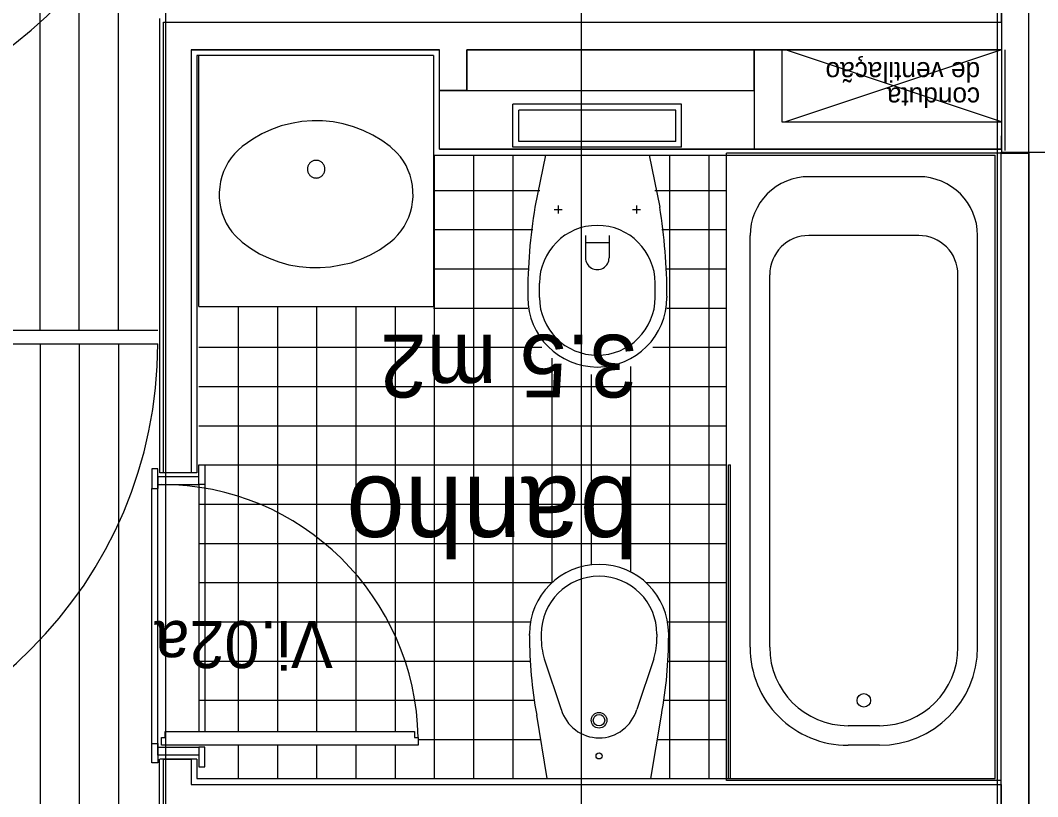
# Model space of a CAD drawing. Extents: x 1248 to 1356, y -443 to -224.
# Drawn here: x 1288.603 to 1291.197, y -234.765 to -232.785 of the extents above; entities that cross this region are included whole.
import ezdxf

# ---------------------------------------------------------------- set-up
doc = ezdxf.new("R2010")
doc.units = 0
for name, color, linetype in [('corte', 7, 'Continuous'), ('estereoctomias', 7, 'Continuous'), ('Level 1', 7, 'Continuous'), ('Level 10', 7, 'Continuous'), ('Level 11', 7, 'Continuous'), ('Level 13', 7, 'Continuous'), ('Level 2', 7, 'Continuous'), ('Level 36', 7, 'Continuous'), ('Level 4', 7, 'Continuous'), ('Level 40', 7, 'Continuous'), ('Level 41', 7, 'Continuous'), ('Level 60', 7, 'Continuous'), ('revestimentos', 7, 'Continuous'), ('vermelhos-tracej', 7, 'Continuous')]:
    doc.layers.add(name, color=color, linetype=linetype)

msp = doc.modelspace()

# ---------------------------------------------------------------- linework, layer by layer
at = {"layer": 'corte'}
for p, q in [((1289.6716, -233.114), (1289.6716, -232.8603)), ((1289.7416, -232.964), (1289.7416, -232.8603)), ((1290.4742, -232.8603), (1290.4742, -233.114)), ((1290.5442, -232.8603), (1291.1042, -232.8603)), ((1290.5442, -232.8603), (1290.5442, -233.044))]:
    msp.add_line(p, q, dxfattribs=at)
msp.add_lwpolyline([(1291.1042, -233.1214), (1291.3342, -233.1214), (1291.3342, -232.3214), (1291.1042, -232.3214)], close=True, dxfattribs=at)
at = {"layer": 'estereoctomias'}
for points in [[(1291.1042, -232.8603), (1289.7416, -232.8603), (1289.7416, -232.964), (1289.6716, -232.964), (1289.6716, -232.8603), (1289.0386, -232.8603), (1289.0386, -233.939), (1288.9686, -233.939), (1288.9686, -232.7903), (1291.1042, -232.7903)], [(1291.1036, -233.114), (1290.4742, -233.114), (1289.6716, -233.114), (1289.6716, -232.964), (1290.4742, -232.964), (1290.4742, -232.8603), (1290.5442, -232.8603), (1290.5442, -233.044), (1291.1042, -233.044)], [(1291.1036, -233.124), (1291.1742, -233.124), (1291.1742, -238.1712), (1291.1042, -238.1713), (1291.1042, -237.4452)], [(1291.1035, -235.0576), (1290.4836, -235.0576), (1290.4836, -234.804), (1289.0385, -234.804), (1289.0385, -234.904), (1288.9685, -234.904), (1288.9685, -234.669), (1289.0386, -234.669), (1289.0386, -234.734), (1291.1035, -234.734), (1291.1035, -234.804), (1290.5536, -234.804), (1290.5536, -234.9876), (1291.1035, -234.9876)]]:
    msp.add_lwpolyline(points, close=True, dxfattribs=at)
at = {"layer": 'Level 1'}
for p, q in [((1291.1042, -232.7903), (1291.1042, -228.764)), ((1291.1742, -239.234), (1291.1742, -228.764)), ((1288.9685, -232.7903), (1291.1042, -232.7903)), ((1288.9686, -233.939), (1288.9686, -232.7903)), ((1289.0386, -232.8603), (1289.0386, -233.939)), ((1289.0386, -232.8603), (1289.6716, -232.8603)), ((1289.7416, -232.8603), (1290.4742, -232.8603)), ((1290.5442, -232.8603), (1291.1042, -232.8603)), ((1291.1135, -233.1176), (1291.1135, -232.8603)), ((1289.6716, -232.964), (1290.4742, -232.964)), ((1290.5442, -233.044), (1291.1042, -233.044)), ((1289.6716, -233.114), (1291.1036, -233.114)), ((1291.1035, -234.804), (1291.1035, -233.1214)), ((1289.0536, -233.939), (1288.9586, -233.939)), ((1289.0536, -234.669), (1288.9586, -234.669)), ((1288.9685, -234.904), (1288.9685, -234.669)), ((1289.0386, -234.669), (1289.0386, -234.734)), ((1289.0386, -234.734), (1291.1035, -234.734))]:
    msp.add_line(p, q, dxfattribs=at)
at = {"layer": 'Level 10'}
for p, q in [((1288.6535, -233.5753), (1288.6535, -232.0103)), ((1288.7535, -233.5753), (1288.7535, -232.0103)), ((1288.8535, -233.5753), (1288.8535, -232.0103)), ((1289.6586, -233.129), (1289.6586, -234.719)), ((1289.7586, -233.129), (1289.7586, -234.719)), ((1289.8586, -233.129), (1289.8586, -234.719)), ((1290.2586, -233.129), (1290.2586, -234.719)), ((1290.3586, -233.129), (1290.3586, -234.719)), ((1289.6566, -233.219), (1289.9278, -233.219)), ((1290.2206, -233.219), (1290.4036, -233.219)), ((1289.6566, -233.319), (1289.9096, -233.319)), ((1290.2389, -233.319), (1290.4036, -233.319)), ((1289.6566, -233.419), (1289.8968, -233.419)), ((1290.2517, -233.419), (1290.4036, -233.419)), ((1289.1586, -233.5153), (1289.1586, -234.599)), ((1289.2586, -233.5153), (1289.2586, -234.599)), ((1289.3586, -233.5153), (1289.3586, -234.599)), ((1289.4586, -233.5153), (1289.4586, -234.599)), ((1289.5586, -233.5153), (1289.5586, -234.599)), ((1289.6566, -233.519), (1289.8969, -233.519)), ((1290.2516, -233.519), (1290.4036, -233.519)), ((1288.6535, -233.6103), (1288.6535, -235.7965)), ((1288.6535, -233.6103), (1288.6535, -235.7965)), ((1288.7535, -233.6103), (1288.7535, -235.7965)), ((1288.8535, -233.6103), (1288.8535, -235.7965)), ((1289.0586, -233.619), (1289.9327, -233.619)), ((1290.2157, -233.619), (1290.4036, -233.619)), ((1289.9586, -233.6465), (1289.9586, -234.2195)), ((1290.0586, -233.6886), (1290.0586, -234.1739)), ((1290.1586, -233.668), (1290.1586, -234.1918)), ((1289.0586, -233.719), (1290.4036, -233.719)), ((1289.0586, -233.819), (1290.4036, -233.819)), ((1289.0586, -233.919), (1290.4036, -233.919)), ((1289.0586, -233.969), (1289.0586, -234.599)), ((1288.9536, -234.629), (1288.9536, -233.979)), ((1289.0586, -234.019), (1290.4036, -234.019)), ((1289.0586, -234.119), (1290.4036, -234.119)), ((1289.0586, -234.219), (1289.9591, -234.219)), ((1290.1981, -234.219), (1290.4036, -234.219)), ((1289.0586, -234.319), (1289.9039, -234.319)), ((1290.2533, -234.319), (1290.4036, -234.319)), ((1289.0586, -234.419), (1289.903, -234.419)), ((1290.2542, -234.419), (1290.4036, -234.419)), ((1289.0586, -234.519), (1289.9133, -234.519)), ((1290.2439, -234.519), (1290.4036, -234.519)), ((1289.6179, -234.619), (1289.9298, -234.619)), ((1290.2273, -234.619), (1290.4036, -234.619)), ((1289.1586, -234.634), (1289.1586, -234.719)), ((1289.2586, -234.634), (1289.2586, -234.719)), ((1289.3586, -234.634), (1289.3586, -234.719)), ((1289.4586, -234.634), (1289.4586, -234.719)), ((1289.5586, -234.634), (1289.5586, -234.719))]:
    msp.add_line(p, q, dxfattribs=at)
at = {"layer": 'Level 11'}
for p, q in [((1289.8592, -233.109), (1289.8592, -232.999)), ((1290.2892, -232.999), (1289.8592, -232.999)), ((1290.2742, -233.014), (1289.8742, -233.014)), ((1289.8742, -233.094), (1289.8742, -233.014)), ((1290.2742, -233.094), (1290.2742, -233.014)), ((1290.2892, -233.109), (1290.2892, -232.999)), ((1289.2432, -233.0637), (1289.2189, -233.0748)), ((1289.2684, -233.0547), (1289.2432, -233.0637)), ((1289.2942, -233.048), (1289.2684, -233.0547)), ((1289.3207, -233.0436), (1289.2942, -233.048)), ((1289.3473, -233.0415), (1289.3207, -233.0436)), ((1289.374, -233.0418), (1289.3473, -233.0415)), ((1289.4005, -233.0444), (1289.374, -233.0418)), ((1289.4267, -233.0494), (1289.4005, -233.0444)), ((1289.4526, -233.0566), (1289.4267, -233.0494)), ((1289.4776, -233.0661), (1289.4526, -233.0566)), ((1289.5016, -233.0778), (1289.4776, -233.0661)), ((1289.1957, -233.0881), (1289.1686, -233.1072)), ((1289.2189, -233.0748), (1289.1957, -233.0881)), ((1289.5246, -233.0915), (1289.5016, -233.0778)), ((1289.5463, -233.1072), (1289.5246, -233.0915)), ((1289.1586, -233.116), (1289.1493, -233.1255)), ((1289.1686, -233.1072), (1289.1586, -233.116)), ((1289.5635, -233.1232), (1289.5463, -233.1072)), ((1290.2892, -233.109), (1289.8592, -233.109)), ((1290.2742, -233.094), (1289.8742, -233.094)), ((1291.1035, -233.114), (1290.4036, -233.114)), ((1289.1409, -233.1359), (1289.1334, -233.147)), ((1289.1493, -233.1255), (1289.1409, -233.1359)), ((1289.348, -233.1444), (1289.3463, -233.1453)), ((1289.3498, -233.1436), (1289.348, -233.1444)), ((1289.3517, -233.143), (1289.3498, -233.1436)), ((1289.3536, -233.1426), (1289.3517, -233.143)), ((1289.3555, -233.1424), (1289.3536, -233.1426)), ((1289.3574, -233.1423), (1289.3555, -233.1424)), ((1289.3594, -233.1424), (1289.3574, -233.1423)), ((1289.3613, -233.1426), (1289.3594, -233.1424)), ((1289.3632, -233.143), (1289.3613, -233.1426)), ((1289.3651, -233.1436), (1289.3632, -233.143)), ((1289.3669, -233.1444), (1289.3651, -233.1436)), ((1289.3686, -233.1453), (1289.3669, -233.1444)), ((1289.5721, -233.1334), (1289.5635, -233.1232)), ((1289.5798, -233.1443), (1289.5721, -233.1334)), ((1289.5866, -233.1558), (1289.5798, -233.1443)), ((1289.9419, -233.129), (1289.9153, -233.2614)), ((1289.9419, -233.129), (1290.2066, -233.129)), ((1290.2066, -233.129), (1290.2332, -233.2614)), ((1291.1036, -233.124), (1290.4036, -233.124)), ((1290.4036, -234.724), (1290.4036, -233.124)), ((1291.1036, -234.724), (1291.1036, -233.124)), ((1289.1214, -233.1709), (1289.117, -233.1835)), ((1289.1269, -233.1587), (1289.1214, -233.1709)), ((1289.1334, -233.147), (1289.1269, -233.1587)), ((1289.3352, -233.1629), (1289.3351, -233.1648)), ((1289.3351, -233.1648), (1289.3352, -233.1668)), ((1289.3355, -233.1609), (1289.3352, -233.1629)), ((1289.3352, -233.1668), (1289.3355, -233.1688)), ((1289.3359, -233.159), (1289.3355, -233.1609)), ((1289.3355, -233.1688), (1289.3359, -233.1707)), ((1289.3365, -233.1571), (1289.3359, -233.159)), ((1289.3359, -233.1707), (1289.3365, -233.1726)), ((1289.3372, -233.1553), (1289.3365, -233.1571)), ((1289.3381, -233.1536), (1289.3372, -233.1553)), ((1289.3392, -233.1519), (1289.3381, -233.1536)), ((1289.3404, -233.1503), (1289.3392, -233.1519)), ((1289.3417, -233.1489), (1289.3404, -233.1503)), ((1289.3431, -233.1476), (1289.3417, -233.1489)), ((1289.3447, -233.1464), (1289.3431, -233.1476)), ((1289.3463, -233.1453), (1289.3447, -233.1464)), ((1289.3702, -233.1464), (1289.3686, -233.1453)), ((1289.3718, -233.1476), (1289.3702, -233.1464)), ((1289.3732, -233.1489), (1289.3718, -233.1476)), ((1289.3745, -233.1503), (1289.3732, -233.1489)), ((1289.3757, -233.1519), (1289.3745, -233.1503)), ((1289.3768, -233.1536), (1289.3757, -233.1519)), ((1289.3777, -233.1553), (1289.3768, -233.1536)), ((1289.3784, -233.1571), (1289.3777, -233.1553)), ((1289.379, -233.159), (1289.3784, -233.1571)), ((1289.3784, -233.1726), (1289.379, -233.1707)), ((1289.3794, -233.1609), (1289.379, -233.159)), ((1289.379, -233.1707), (1289.3794, -233.1688)), ((1289.3797, -233.1629), (1289.3794, -233.1609)), ((1289.3794, -233.1688), (1289.3797, -233.1668)), ((1289.3798, -233.1648), (1289.3797, -233.1629)), ((1289.3797, -233.1668), (1289.3798, -233.1648)), ((1289.5923, -233.1679), (1289.5866, -233.1558)), ((1289.597, -233.1805), (1289.5923, -233.1679)), ((1289.1137, -233.1965), (1289.1115, -233.2097)), ((1289.117, -233.1835), (1289.1137, -233.1965)), ((1289.3365, -233.1726), (1289.3372, -233.1744)), ((1289.3372, -233.1744), (1289.3381, -233.1761)), ((1289.3381, -233.1761), (1289.3392, -233.1778)), ((1289.3392, -233.1778), (1289.3404, -233.1793)), ((1289.3404, -233.1793), (1289.3417, -233.1808)), ((1289.3417, -233.1808), (1289.3431, -233.1821)), ((1289.3431, -233.1821), (1289.3447, -233.1833)), ((1289.3447, -233.1833), (1289.3463, -233.1844)), ((1289.3463, -233.1844), (1289.348, -233.1853)), ((1289.348, -233.1853), (1289.3498, -233.186)), ((1289.3498, -233.186), (1289.3517, -233.1866)), ((1289.3517, -233.1866), (1289.3536, -233.1871)), ((1289.3536, -233.1871), (1289.3555, -233.1873)), ((1289.3555, -233.1873), (1289.3574, -233.1874)), ((1289.3574, -233.1874), (1289.3594, -233.1873)), ((1289.3594, -233.1873), (1289.3613, -233.1871)), ((1289.3613, -233.1871), (1289.3632, -233.1866)), ((1289.3632, -233.1866), (1289.3651, -233.186)), ((1289.3651, -233.186), (1289.3669, -233.1853)), ((1289.3669, -233.1853), (1289.3686, -233.1844)), ((1289.3686, -233.1844), (1289.3702, -233.1833)), ((1289.3702, -233.1833), (1289.3718, -233.1821)), ((1289.3718, -233.1821), (1289.3732, -233.1808)), ((1289.3732, -233.1808), (1289.3745, -233.1793)), ((1289.3745, -233.1793), (1289.3757, -233.1778)), ((1289.3757, -233.1778), (1289.3768, -233.1761)), ((1289.3768, -233.1761), (1289.3777, -233.1744)), ((1289.3777, -233.1744), (1289.3784, -233.1726)), ((1289.6005, -233.1934), (1289.597, -233.1805)), ((1289.603, -233.2066), (1289.6005, -233.1934)), ((1290.8936, -233.184), (1290.6136, -233.184)), ((1289.1115, -233.2097), (1289.1105, -233.2244)), ((1289.6043, -233.2212), (1289.603, -233.2066)), ((1289.6044, -233.235), (1289.6043, -233.2212)), ((1289.1105, -233.2244), (1289.1106, -233.2382)), ((1289.1106, -233.2382), (1289.1119, -233.2516)), ((1289.6012, -233.2616), (1289.6034, -233.2484)), ((1289.6034, -233.2484), (1289.6044, -233.235)), ((1289.1119, -233.2516), (1289.1144, -233.2648)), ((1289.1144, -233.2648), (1289.1179, -233.2777)), ((1289.5935, -233.2873), (1289.5979, -233.2746)), ((1289.5979, -233.2746), (1289.6012, -233.2616)), ((1289.9642, -233.2675), (1289.9842, -233.2675)), ((1289.9742, -233.2575), (1289.9742, -233.2775)), ((1290.1642, -233.2675), (1290.1842, -233.2675)), ((1290.1742, -233.2575), (1290.1742, -233.2775)), ((1289.1179, -233.2777), (1289.1226, -233.2902)), ((1289.1226, -233.2902), (1289.1283, -233.3023)), ((1289.5815, -233.3112), (1289.588, -233.2995)), ((1289.588, -233.2995), (1289.5935, -233.2873)), ((1289.1283, -233.3023), (1289.1351, -233.3139)), ((1289.1351, -233.3139), (1289.1428, -233.3248)), ((1289.1428, -233.3248), (1289.1514, -233.335)), ((1289.5656, -233.3326), (1289.574, -233.3222)), ((1289.574, -233.3222), (1289.5815, -233.3112)), ((1289.1514, -233.335), (1289.1686, -233.3509)), ((1289.1686, -233.3509), (1289.1903, -233.3666)), ((1289.5192, -233.3701), (1289.5463, -233.3509)), ((1289.5463, -233.3509), (1289.5563, -233.3422)), ((1289.5563, -233.3422), (1289.5656, -233.3326)), ((1290.0442, -233.3338), (1290.0442, -233.391)), ((1290.0442, -233.3515), (1290.1042, -233.3515)), ((1290.1042, -233.3338), (1290.1042, -233.3911)), ((1290.4636, -234.384), (1290.4636, -233.334)), ((1290.8936, -233.334), (1290.6136, -233.334)), ((1291.0436, -234.384), (1291.0436, -233.334)), ((1289.1903, -233.3666), (1289.2133, -233.3803)), ((1289.496, -233.3833), (1289.5192, -233.3701)), ((1289.2133, -233.3803), (1289.2373, -233.392)), ((1289.2373, -233.392), (1289.2623, -233.4015)), ((1289.2623, -233.4015), (1289.288, -233.4087)), ((1289.4205, -233.4091), (1289.4465, -233.4034)), ((1289.4465, -233.4034), (1289.4717, -233.3945)), ((1289.4717, -233.3945), (1289.496, -233.3833)), ((1289.288, -233.4087), (1289.3144, -233.4127)), ((1289.3144, -233.4127), (1289.3409, -233.4153)), ((1289.3409, -233.4153), (1289.3676, -233.4156)), ((1289.3676, -233.4156), (1289.3942, -233.4135)), ((1289.3942, -233.4135), (1289.4205, -233.4091)), ((1289.9267, -233.4918), (1289.9267, -233.4557)), ((1290.2217, -233.4918), (1290.2217, -233.4557)), ((1290.5136, -234.384), (1290.5136, -233.434)), ((1290.9936, -234.384), (1290.9936, -233.434)), ((1289.8967, -233.4884), (1289.8967, -233.4921)), ((1290.2517, -233.4884), (1290.2517, -233.4921)), ((1289.9011, -234.3536), (1289.9011, -234.3499)), ((1289.9311, -234.3502), (1289.9311, -234.3583)), ((1290.2261, -234.3502), (1290.2261, -234.3583)), ((1290.2561, -234.3536), (1290.2561, -234.3499)), ((1289.9388, -234.4132), (1289.9824, -234.5424)), ((1290.2184, -234.4132), (1290.1747, -234.5424)), ((1289.9463, -234.719), (1289.9196, -234.5569)), ((1290.2109, -234.719), (1290.2375, -234.5569)), ((1290.7936, -234.584), (1290.7136, -234.584)), ((1290.7936, -234.634), (1290.7136, -234.634)), ((1289.9463, -234.719), (1290.2109, -234.719)), ((1291.1036, -234.724), (1290.4036, -234.724))]:
    msp.add_line(p, q, dxfattribs=at)
for centre, radius in [((1290.7536, -234.5195), 0.0173), ((1290.0786, -234.5701), 0.02), ((1290.0786, -234.5701), 0.0146), ((1290.0786, -234.661), 0.00766)]:
    msp.add_circle(centre, radius, dxfattribs=at)
for centre, radius, start, end in [((1290.6136, -233.334), 0.15, 89.9999, 180.0002), ((1290.8936, -233.334), 0.15, 360, 90), ((1291.2967, -233.4884), 1.4, 170.6656, 180.0002), ((1288.8517, -233.4884), 1.4, 359.9999, 9.3345), ((1290.0742, -233.4557), 0.1475, 0.0002, 179.9999), ((1290.6136, -233.434), 0.1, 90.0001, 179.9999), ((1290.8936, -233.434), 0.1, 360, 90.0001), ((1290.0742, -233.3909), 0.03, 179.9995, 0.0013), ((1290.0742, -233.4918), 0.1775, 180.0002, 359.9999), ((1290.0742, -233.4918), 0.1475, 180.0002, 359.9999), ((1290.0786, -234.3502), 0.1775, 0.0001, 179.9998), ((1290.0786, -234.3502), 0.1475, 0.0001, 179.9998), ((1290.1311, -234.3583), 0.2, 179.9994, 195.9307), ((1290.0261, -234.3583), 0.2, 344.0681, 359.9983), ((1290.7136, -234.384), 0.25, 180, 270.0001), ((1290.7136, -234.384), 0.2, 180, 270), ((1290.7936, -234.384), 0.25, 269.9999, 359.9999), ((1290.7936, -234.384), 0.2, 270, 0), ((1290.0786, -234.515), 0.1, 195.8047, 344.0683)]:
    msp.add_arc(centre, radius, start, end, dxfattribs=at)
for centre, major_axis, start_param, end_param in [((1291.3011, -234.3536), (-1.4, 0), 6.283183, 6.446102), ((1288.8561, -234.3536), (1.4, 0), 6.120269, 6.283187)]:
    msp.add_ellipse(centre, major_axis=major_axis, ratio=0.895428, start_param=start_param, end_param=end_param, dxfattribs=at)
at = {"layer": 'Level 13'}
for p, q in [((1287.8486, -233.5753), (1288.9535, -233.5753)), ((1287.8486, -233.6103), (1288.9535, -233.6103)), ((1289.0586, -233.969), (1289.0586, -233.919)), ((1289.0586, -233.919), (1289.0736, -233.919)), ((1289.0736, -233.919), (1289.0736, -233.969)), ((1288.9386, -233.929), (1288.9386, -233.979)), ((1288.9536, -233.929), (1288.9386, -233.929)), ((1288.9536, -233.979), (1288.9536, -233.929)), ((1289.0586, -233.949), (1288.9536, -233.949)), ((1288.9536, -233.949), (1288.9536, -233.979)), ((1289.0586, -233.969), (1289.0586, -233.949)), ((1288.9536, -233.969), (1289.0586, -233.969)), ((1289.0736, -233.969), (1289.0586, -233.969)), ((1288.9386, -233.979), (1288.9536, -233.979)), ((1288.9629, -234.634), (1288.9629, -234.614)), ((1288.9629, -234.614), (1288.9729, -234.614)), ((1288.9729, -234.599), (1289.6079, -234.599)), ((1288.9729, -234.614), (1288.9729, -234.599)), ((1289.6079, -234.599), (1289.6079, -234.614)), ((1289.6079, -234.614), (1289.6176, -234.614)), ((1289.6179, -234.614), (1289.6179, -234.634)), ((1288.9386, -234.679), (1288.9386, -234.629)), ((1288.9386, -234.629), (1288.9536, -234.629)), ((1288.9536, -234.659), (1288.9536, -234.629)), ((1288.9536, -234.629), (1288.9536, -234.679)), ((1288.9536, -234.639), (1289.0586, -234.639)), ((1289.6179, -234.634), (1288.9629, -234.634)), ((1289.0586, -234.639), (1289.0586, -234.659)), ((1289.0736, -234.639), (1289.0586, -234.639)), ((1289.0586, -234.639), (1289.0586, -234.689)), ((1289.0736, -234.689), (1289.0736, -234.639)), ((1289.0586, -234.659), (1288.9536, -234.659)), ((1288.9536, -234.679), (1288.9386, -234.679)), ((1289.0586, -234.689), (1289.0736, -234.689))]:
    msp.add_line(p, q, dxfattribs=at)
at = {"layer": 'Level 2'}
for p, q in [((1289.0586, -233.5153), (1289.0586, -232.8753)), ((1289.6566, -232.8753), (1289.6566, -233.5153)), ((1289.0586, -233.5153), (1289.6566, -233.5153))]:
    msp.add_line(p, q, dxfattribs=at)
at = {"layer": 'Level 36'}
for p, q in [((1290.4086, -234.719), (1290.4086, -233.919)), ((1290.4086, -233.919), (1290.4136, -233.919)), ((1290.4136, -234.719), (1290.4136, -233.919))]:
    msp.add_line(p, q, dxfattribs=at)
at = {"layer": 'Level 4'}
for p, q in [((1289.0736, -233.969), (1289.0736, -234.599)), ((1288.9386, -234.629), (1288.9386, -233.979))]:
    msp.add_line(p, q, dxfattribs=at)
msp.add_arc((1287.8535, -233.6103), 1.1, 270, 0, dxfattribs=at)
for centre, major_axis, ratio, start_param, end_param in [((1287.8442, -232.0103), (-1.165, 0), 0.93133, 1.578735, 3.141609), ((1288.9629, -234.6276), (0, -0.6586), 0.994276, 1.591512, 3.141593)]:
    msp.add_ellipse(centre, major_axis=major_axis, ratio=ratio, start_param=start_param, end_param=end_param, dxfattribs=at)
at = {"layer": 'Level 41'}
for p, q in [((1291.1042, -233.044), (1290.5543, -232.8603)), ((1291.1042, -232.8603), (1290.5543, -233.044))]:
    msp.add_line(p, q, dxfattribs=at)
at = {"layer": 'revestimentos'}
for p, q in [((1288.9586, -233.939), (1288.9586, -232.7803)), ((1289.6566, -232.8753), (1289.0536, -232.8753)), ((1289.0536, -232.8753), (1289.0536, -233.939)), ((1289.6566, -233.129), (1291.0885, -233.129)), ((1291.0885, -234.719), (1291.0885, -233.129)), ((1288.9585, -234.904), (1288.9585, -234.669)), ((1289.0536, -234.669), (1289.0536, -234.719)), ((1289.0536, -234.719), (1291.0885, -234.719))]:
    msp.add_line(p, q, dxfattribs=at)
at = {"layer": 'vermelhos-tracej'}
for p, q in [((1288.9741, -234.928), (1288.9741, -224.3117)), ((1290.034, -234.928), (1290.034, -224.3117)), ((1291.094, -234.928), (1291.094, -224.3117))]:
    msp.add_line(p, q, dxfattribs=at)

# ---------------------------------------------------------------- texts
at = {"layer": 'Level 40'}
msp.add_text('Vi.02a', height=0.12, rotation=180, dxfattribs=at).set_placement((1289.4001, -234.3171))
at = {"layer": 'Level 41'}
for s, p in [('de ventilação ', (1291.0501, -232.8918)), ('conduta', (1291.0501, -232.9563))]:
    msp.add_text(s, height=0.05, rotation=180, dxfattribs=at).set_placement(p)
at = {"layer": 'Level 60'}
for s, height, p in [('3.5 m2', 0.16, (1290.1743, -233.587)), ('banho', 0.2, (1290.1781, -233.9491))]:
    msp.add_text(s, height=height, rotation=180, dxfattribs=at).set_placement(p)

doc.saveas('drawing.dxf')
